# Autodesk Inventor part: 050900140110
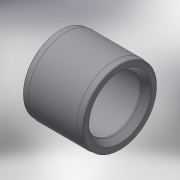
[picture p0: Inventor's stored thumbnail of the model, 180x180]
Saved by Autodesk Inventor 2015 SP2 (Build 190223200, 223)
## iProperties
Created: 2017-11
Part Number: 050900140110
Material: Generic
Description: PLASSON BUSHING-CEMENT PVC 140-110
Document SubType Name: Modeling
Designer: KIM
Density: 1 g/cm^3
Appearance: Default
Author: KIM
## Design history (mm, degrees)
derived "050900.ipt"
feature "Solid1::050900.ipt"
tag "TaggingFeature1"
body "Solid1"
other parameters: "d2" = 61, "d3" = 76, "d7" = 7.6, "d11" = 7.6, "d12" = 1.4, "d14" = 1.4, "d15" = 7.6, "d17" = 1.4, "d18" = 1.4, "d19" = 97.9, "d20" = 3, "d21" = 12.63, "L_" = 76, "l_" = 61, "z_" = 2
